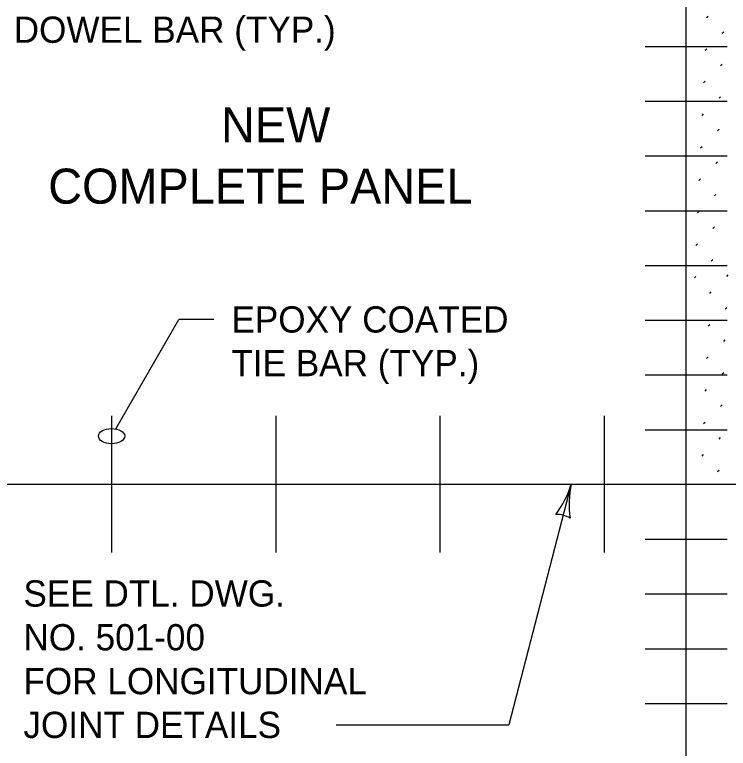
# Model space of a CAD drawing. Extents: x 49991.4 to 50021, y 49987.6 to 50011.4.
# Drawn here: x 50004.526 to 50006.156, y 49995.687 to 49997.362 of the extents above; entities that cross this region are included whole.
import ezdxf

# ---------------------------------------------------------------- set-up
doc = ezdxf.new("R2010")
doc.units = 0
for name, color, linetype in [('Level 1', 7, 'Continuous'), ('Level 10', 7, 'Continuous'), ('Level 2', 7, 'Continuous'), ('Level 3', 7, 'Continuous'), ('Level 4', 7, 'Continuous')]:
    doc.layers.add(name, color=color, linetype=linetype)

msp = doc.modelspace()

# ---------------------------------------------------------------- linework, layer by layer
at = {"layer": 'Level 1'}
for p, q in [((50006.0598, 49994.7903), (50006.0598, 49997.7903)), ((50002.3098, 49996.2901), (50007.9348, 49996.2901))]:
    msp.add_line(p, q, dxfattribs=at)
at = {"layer": 'Level 10'}
for p, q in [((50006.1068, 49997.3547), (50006.1103, 49997.3582)), ((50006.1422, 49997.3194), (50006.1457, 49997.3229)), ((50006.1033, 49997.2805), (50006.1068, 49997.284)), ((50006.1386, 49997.2451), (50006.1421, 49997.2486)), ((50006.0997, 49997.2062), (50006.1032, 49997.2097)), ((50006.1351, 49997.1708), (50006.1386, 49997.1744)), ((50006.0962, 49997.1319), (50006.0997, 49997.1355)), ((50006.1315, 49997.0966), (50006.1351, 49997.1001)), ((50006.0926, 49997.0577), (50006.0962, 49997.0612)), ((50006.128, 49997.0223), (50006.1315, 49997.0259)), ((50006.0891, 49996.9834), (50006.0926, 49996.987)), ((50006.1244, 49996.9481), (50006.128, 49996.9516)), ((50006.0855, 49996.9092), (50006.0891, 49996.9127)), ((50006.1209, 49996.8738), (50006.1244, 49996.8774)), ((50006.082, 49996.8349), (50006.0855, 49996.8385)), ((50006.1174, 49996.7996), (50006.1209, 49996.8031)), ((50006.0788, 49996.761), (50006.082, 49996.7642)), ((50006.1527, 49996.7642), (50006.1562, 49996.7678)), ((50006.1138, 49996.7253), (50006.1173, 49996.7289)), ((50006.1492, 49996.69), (50006.1527, 49996.6935)), ((50006.1103, 49996.6511), (50006.1138, 49996.6546)), ((50006.1456, 49996.6157), (50006.1492, 49996.6193)), ((50006.1067, 49996.5768), (50006.1103, 49996.5804)), ((50006.1421, 49996.5415), (50006.1456, 49996.545)), ((50006.1032, 49996.5026), (50006.1067, 49996.5061)), ((50006.1385, 49996.4672), (50006.1421, 49996.4707)), ((50006.0996, 49996.4283), (50006.1032, 49996.4318)), ((50006.135, 49996.393), (50006.1385, 49996.3965)), ((50006.0961, 49996.3541), (50006.0996, 49996.3576)), ((50006.1315, 49996.3187), (50006.135, 49996.3222)), ((50005.2601, 49995.7404), (50005.6546, 49995.7404))]:
    msp.add_line(p, q, dxfattribs=at)
msp.add_ellipse((50004.7473, 49996.3996), major_axis=(0.03, 0), ratio=0.57735, dxfattribs=at)
at = {"layer": 'Level 3'}
for p, q in [((50004.7568, 49996.4161), (50004.9011, 49996.666)), ((50004.9811, 49996.666), (50004.9011, 49996.666)), ((50005.7975, 49996.2903), (50005.6546, 49995.7404))]:
    msp.add_line(p, q, dxfattribs=at)
for centre, radius, start, end in [((50005.5848, 49996.3548), 0.2223, 322.8948, 343.0783), ((50006.0256, 49996.2427), 0.233, 168.2661, 187.5159), ((50005.7652, 49996.166), 0.0548, 57.5776, 93.2999)]:
    msp.add_arc(centre, radius, start, end, dxfattribs=at)
at = {"layer": 'Level 4'}
for p, q in [((50005.966, 49997.2892), (50006.1535, 49997.2892)), ((50005.966, 49997.1642), (50006.1535, 49997.1642)), ((50005.966, 49997.0392), (50006.1535, 49997.0392)), ((50005.966, 49996.9142), (50006.1535, 49996.9142)), ((50005.966, 49996.7892), (50006.1535, 49996.7892)), ((50005.966, 49996.6642), (50006.1535, 49996.6642)), ((50005.966, 49996.5392), (50006.1535, 49996.5392)), ((50004.7473, 49996.4463), (50004.7473, 49996.1338)), ((50005.1223, 49996.4463), (50005.1223, 49996.1338)), ((50005.4973, 49996.4463), (50005.4973, 49996.1338)), ((50005.8723, 49996.4463), (50005.8723, 49996.1338)), ((50005.966, 49996.4142), (50006.1535, 49996.4142)), ((50005.966, 49996.1642), (50006.1535, 49996.1642)), ((50005.966, 49996.0392), (50006.1535, 49996.0392)), ((50005.966, 49995.9142), (50006.1535, 49995.9142)), ((50005.966, 49995.7892), (50006.1535, 49995.7892))]:
    msp.add_line(p, q, dxfattribs=at)

# ---------------------------------------------------------------- texts
at = {"layer": 'Level 2'}
for s, height, p in [('DOWEL BAR (TYP.)', 0.06, (50004.5238, 49997.2975)), ('NEW', 0.08, (50004.9975, 49997.0703)), ('COMPLETE PANEL', 0.08, (50004.6027, 49996.9303)), ('EPOXY COATED ', 0.06, (50005.0211, 49996.636)), ('TIE BAR (TYP.)', 0.06, (50005.0211, 49996.5364)), ('SEE DTL. DWG. ', 0.06, (50004.546, 49996.0104)), ('NO. 501-00', 0.06, (50004.546, 49995.9104)), ('FOR LONGITUDINAL', 0.06, (50004.546, 49995.8104)), ('JOINT DETAILS', 0.06, (50004.546, 49995.7104))]:
    msp.add_text(s, height=height, dxfattribs=at).set_placement(p)

doc.saveas('drawing.dxf')
